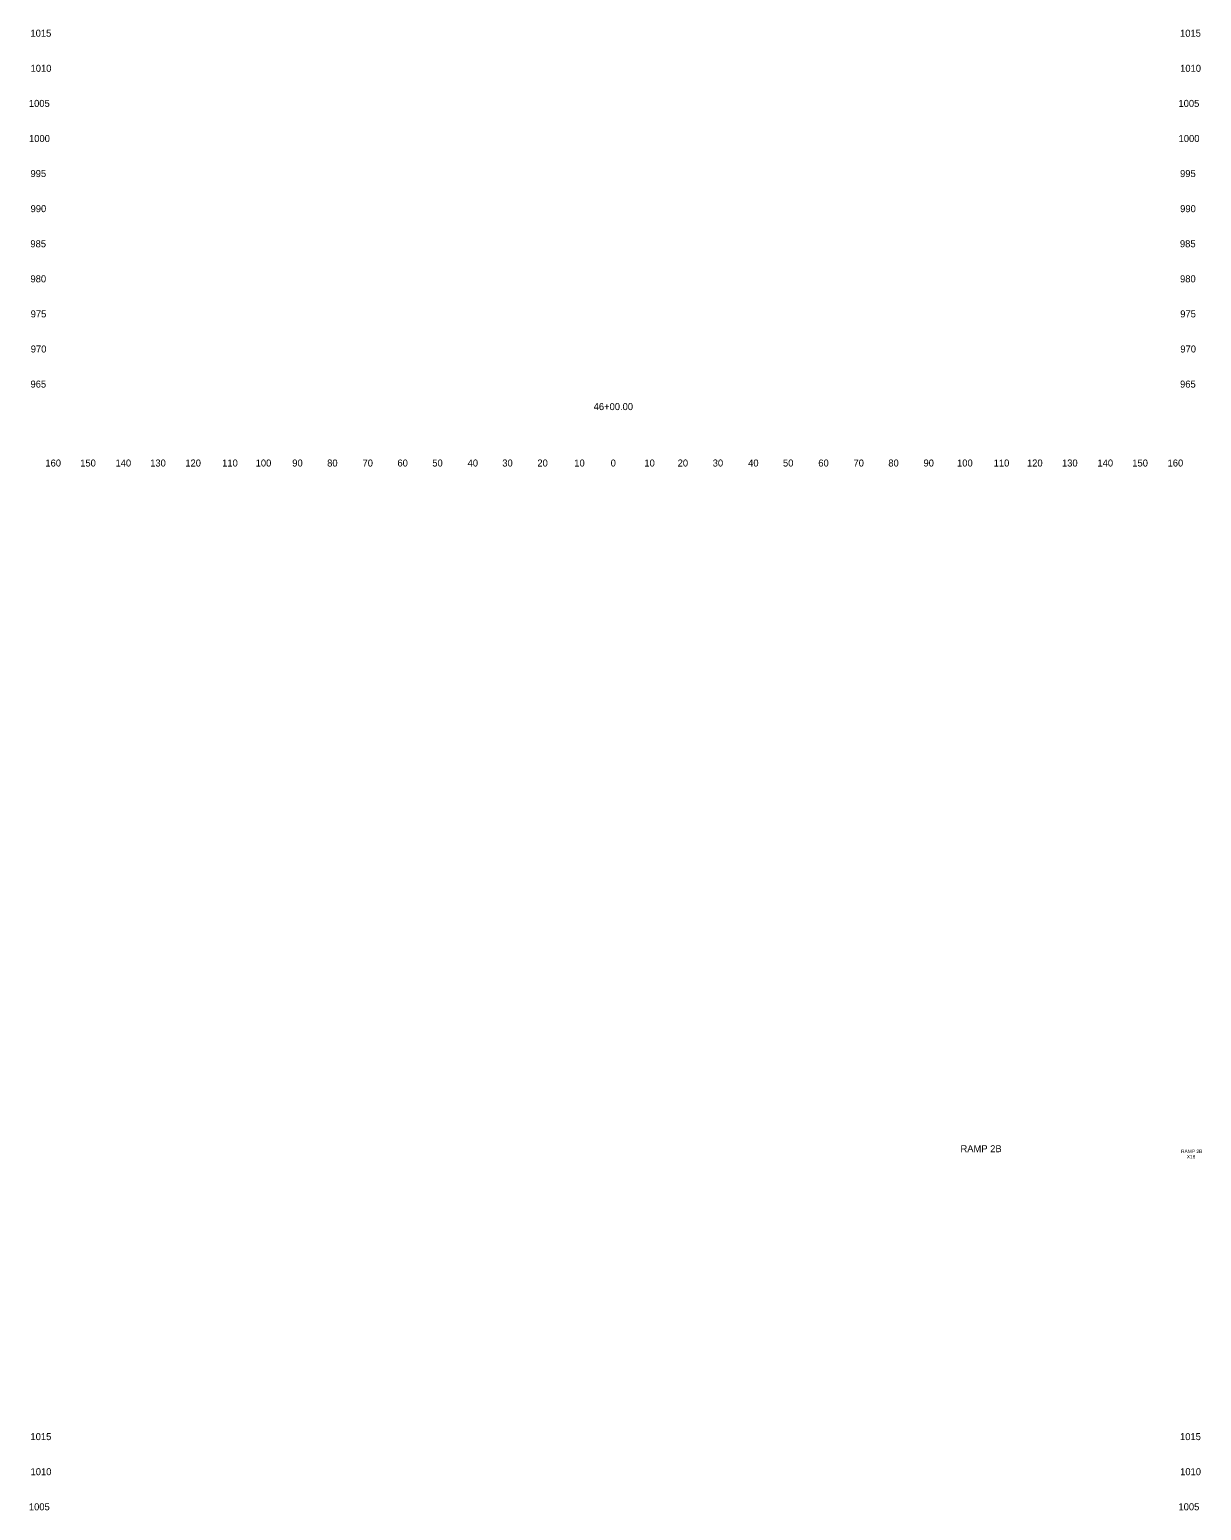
# Model space of a CAD drawing. Extents: x 4994 to 6358, y 4997 to 8804.
# Drawn here: x 5508.6 to 5842.7, y 7900 to 8322 of the extents above; entities that cross this region are included whole.
import ezdxf

# ---------------------------------------------------------------- set-up
doc = ezdxf.new("R2010")
doc.units = 0
for name, color, linetype in [('RD_SHT_ID', 7, 'Continuous'), ('RD_XS_TX_Offset', 7, 'Continuous'), ('RD_XS_TX_Station', 7, 'Continuous')]:
    doc.layers.add(name, color=color, linetype=linetype)

msp = doc.modelspace()

# ---------------------------------------------------------------- texts
at = {"layer": 'RD_SHT_ID'}
for s, height, p in [('RAMP 2B', 2, (5774.05, 8002.06)), ('RAMP 2B', 1, (5836.94, 8001.8)), ('X18', 1, (5838.57, 8000.3))]:
    msp.add_text(s, height=height, dxfattribs=at).set_placement(p)
at = {"layer": 'RD_XS_TX_Offset'}
for s, p in [('1015', (5508.85, 8320)), ('1015', (5836.65, 8320)), ('1010', (5508.88, 8310)), ('1010', (5836.68, 8310)), ('1005', (5508.4, 8300)), ('1005', (5836.2, 8300)), ('1000', (5508.44, 8290)), ('1000', (5836.24, 8290)), ('995', (5508.86, 8280)), ('995', (5836.66, 8280)), ('990', (5508.89, 8270)), ('990', (5836.69, 8270)), ('985', (5508.83, 8260)), ('985', (5836.63, 8260)), ('980', (5508.86, 8250)), ('980', (5836.66, 8250)), ('975', (5508.91, 8240)), ('975', (5836.71, 8240)), ('970', (5508.94, 8230)), ('970', (5836.74, 8230)), ('965', (5508.86, 8220)), ('965', (5836.66, 8220)), ('160', (5513.1, 8197.5)), ('150', (5523.04, 8197.5)), ('140', (5533.1, 8197.5)), ('130', (5542.99, 8197.5)), ('120', (5553.01, 8197.5)), ('110', (5563.51, 8197.5)), ('100', (5573.07, 8197.5)), ('90', (5583.5, 8197.5)), ('80', (5593.46, 8197.5)), ('70', (5603.54, 8197.5)), ('60', (5613.5, 8197.5)), ('50', (5623.43, 8197.5)), ('40', (5633.5, 8197.5)), ('30', (5643.39, 8197.5)), ('20', (5653.4, 8197.5)), ('10', (5663.91, 8197.5)), ('0', (5674.3, 8197.5)), ('0', (5674.3, 8197.5)), ('10', (5683.91, 8197.5)), ('20', (5693.4, 8197.5)), ('30', (5703.39, 8197.5)), ('40', (5713.5, 8197.5)), ('50', (5723.43, 8197.5)), ('60', (5733.5, 8197.5)), ('70', (5743.54, 8197.5)), ('80', (5753.46, 8197.5)), ('90', (5763.5, 8197.5)), ('100', (5773.07, 8197.5)), ('110', (5783.51, 8197.5)), ('120', (5793.01, 8197.5)), ('130', (5802.99, 8197.5)), ('140', (5813.1, 8197.5)), ('150', (5823.04, 8197.5)), ('160', (5833.1, 8197.5)), ('1015', (5508.85, 7920)), ('1015', (5836.65, 7920)), ('1010', (5508.88, 7910)), ('1010', (5836.68, 7910)), ('1005', (5508.4, 7900)), ('1005', (5836.2, 7900))]:
    msp.add_text(s, height=2, dxfattribs=at).set_placement(p)
at = {"layer": 'RD_XS_TX_Station'}
msp.add_text('46+00.00', height=2, dxfattribs=at).set_placement((5669.45, 8213.58))

doc.saveas('drawing.dxf')
